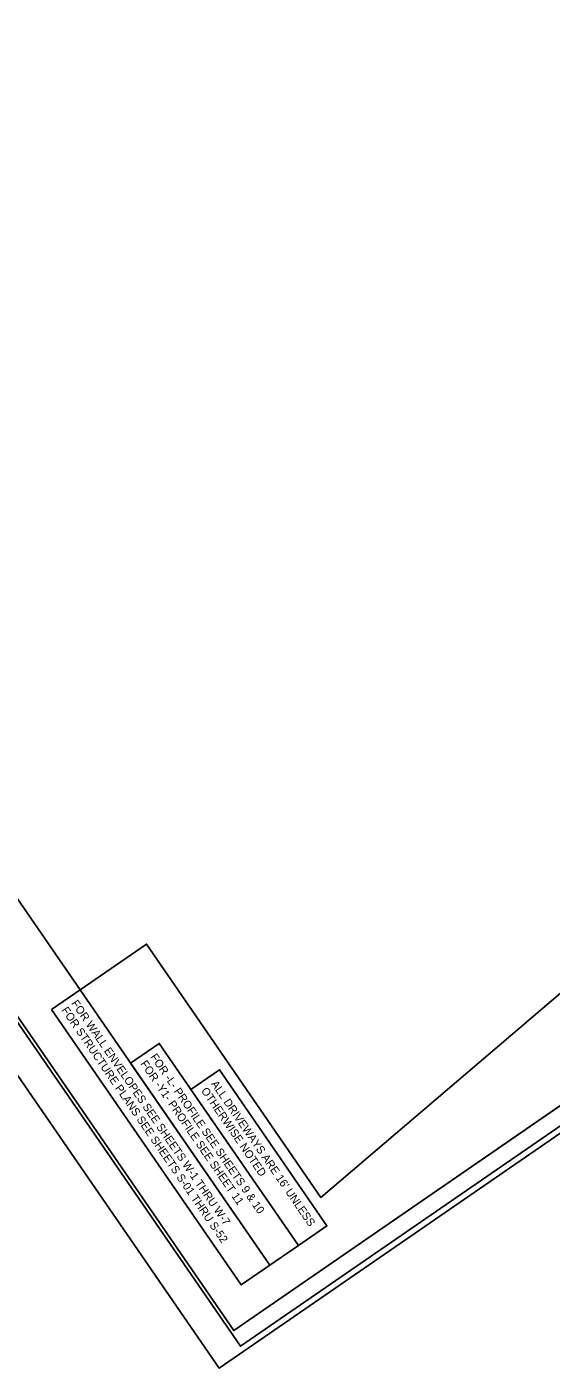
# Model space of a CAD drawing. Extents: x 2297526 to 2298642, y 599613 to 600819.
# Drawn here: x 2298012 to 2298248, y 599613 to 600216 of the extents above; entities that cross this region are included whole.
import ezdxf

# ---------------------------------------------------------------- set-up
doc = ezdxf.new("R2010")
doc.units = 0
for name, color, linetype in [('Exist DTM Drainline Cogo Comment', 7, 'Continuous'), ('Exist DTM Drainline Cogo Elevation', 7, 'Continuous'), ('Exist Property Iron Pin Cogo Number', 7, 'Continuous'), ('Exist Roads Curbs Cogo Number', 7, 'Continuous'), ('Exist Roads Curbs Cogo Point CELL', 7, 'Continuous'), ('Exist Roads EOP Cogo Elevation', 7, 'Continuous'), ('Exist Roads EOP Cogo Number', 7, 'Continuous')]:
    doc.layers.add(name, color=color, linetype=linetype)

msp = doc.modelspace()

# ---------------------------------------------------------------- linework, layer by layer
at = {"layer": 'Exist DTM Drainline Cogo Comment'}
msp.add_lwpolyline([(2298629.8, 599981.76), (2298062.67, 600805.27), (2297541.29, 600446.21), (2298108.42, 599622.7)], close=True, dxfattribs=at)
at = {"layer": 'Exist DTM Drainline Cogo Elevation'}
msp.add_lwpolyline([(2298624.28, 599987.07), (2298113.82, 600728.3), (2297594.96, 600370.97), (2298105.42, 599629.74)], close=True, dxfattribs=at)
at = {"layer": 'Exist Property Iron Pin Cogo Number'}
msp.add_lwpolyline([(2297647.43, 600347.7), (2298036.32, 599783), (2298066.14, 599803.53), (2298144.6, 599689.59), (2298480.39, 599975.84), (2298444.85, 600027.45), (2298522.99, 600081.26), (2298287.23, 600423.6), (2298114.33, 600674.66)], close=True, dxfattribs=at)
at = {"layer": 'Exist Roads Curbs Cogo Number'}
msp.add_lwpolyline([(2298113.82, 600728.3), (2297594.98, 600370.97), (2298105.44, 599629.74), (2298525.54, 599919.07), (2298457.47, 600017.93), (2298556.21, 600085.92)], close=True, dxfattribs=at)
at = {"layer": 'Exist Roads Curbs Cogo Point CELL'}
msp.add_lwpolyline([(2298642.42, 599987.17), (2298069.34, 600819.33), (2297525.77, 600444.99), (2298098.85, 599612.83)], close=True, dxfattribs=at)
at = {"layer": 'Exist Roads EOP Cogo Number'}
for points in [[(2298023.46, 599774.14), (2298108.77, 599650.26), (2298121.62, 599659.11), (2298036.31, 599782.99)], [(2298059, 599750.05), (2298121.62, 599659.11), (2298134.48, 599667.96), (2298071.85, 599758.9)], [(2298086.14, 599738.16), (2298134.48, 599667.96), (2298147.33, 599676.82), (2298098.99, 599747.01)]]:
    msp.add_lwpolyline(points, close=True, dxfattribs=at)

# ---------------------------------------------------------------- texts
at = {"layer": 'Exist Roads EOP Cogo Elevation'}
for s, p in [('FOR STRUCTURE PLANS SEE SHEETS S-01 THRU S-52', (2298027.69, 599773.82)), ('FOR WALL ENVELOPES SEE SHEETS W-1 THRU W-7', (2298032.13, 599776.89)), ('FOR -Y1- PROFILE SEE SHEET 11', (2298063.23, 599749.73)), ('FOR -L- PROFILE SEE SHEETS 9 & 10', (2298067.67, 599752.79)), ('OTHERWISE NOTED', (2298090.53, 599737.6)), ("ALL DRIVEWAYS ARE 16' UNLESS ", (2298094.98, 599740.66))]:
    msp.add_text(s, height=3.6, rotation=304.55406, dxfattribs=at).set_placement(p)

doc.saveas('drawing.dxf')
